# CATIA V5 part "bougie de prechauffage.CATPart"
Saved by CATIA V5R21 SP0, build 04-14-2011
Part number: bougie de prechauffage
Material "Laiton": density 8216 kg/m3, Young's modulus 1.31e+11 Pa, Poisson ratio 0.35, thermal expansion 1.67e-05 1/K
Bounding box of the stored display mesh (mm): x -4 to 4, y -4.619 to 4.619, z 0 to 15.5
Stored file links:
  C:\Users\Olivier\Desktop\redaction CATIA (local)\pompe à moteur de ventilation refait\bougie de prechauffage.CATPart
  C:\Program Files\Dassault Systemes\B21\win_b64\startup\materials\French\Catalog.CATMaterial
  C:\Users\Olivier\Desktop\redaction CATIA (local)\pompe à moteur de ventilation refait\Pompe_a_moteur_de_ventilation.CATProduct
  C:\Users\Olivier\Desktop\redaction CATIA (local)\pompe à moteur de ventilation refait\Ecrou a collerette M5.CATPart
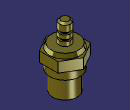
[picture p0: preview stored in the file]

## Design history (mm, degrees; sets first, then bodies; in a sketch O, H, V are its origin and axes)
Body1 (main body), material "Laiton"
  Sketch1 on yz-plane, origin (0, 0, 0), H (0, 1, 0), V (0, 0, 1)
    point P1 (3.021, 0)
    line L1 (3, 5) -> (3.75, 5)
    line L2 (3.75, 5) -> (3.75, 9.5)
    line L3 (3.75, 9.5) -> (3.3999, 10.5)
    line L4 (3.3999, 10.5) -> (1.4, 10.5)
    line L5 (1.4, 10.5) -> (1.4, 11.4933)
    line L6 (1.4, 11.4933) -> (0.9847, 11.4933)
    line L7 (0.9847, 11.4933) -> (0.9847, 11.9933)
    line L8 (0.9847, 11.9933) -> (1.4, 11.9933)
    point P10 (1.4, 11.9933)
    line L9 (1.4, 11.9933) -> (1.4, 12.9933)
    line L10 (1.4, 12.9933) -> (0.9847, 12.9933)
    point P12 (0.9847, 12.9933)
    line L11 (0.9847, 12.9933) -> (0.9847, 13.4933)
    line L12 (0.9847, 13.4933) -> (1.4, 13.4933)
    point P14 (1.4, 13.4933)
    line L13 (2.5869, 0) -> (1.25, 0)
    line L14 (1.25, 0) -> (1.25, 4)
    line L15 (1.25, 4) -> (0, 4)
    point P17 (0, 4)
    line L16 (3, 5) -> (3.02, 0.25)
    line L17 (2.5869, 0) -> (3.02, 0.25)
    line L18 (1.4, 13.4933) -> (1.4, 15.0655)
    point P20 (1.4, 15.5)
    line L19 (0.9655, 15.5) -> (0, 15.5)
    point P21 (0, 15.5)
    line L20 (0.9655, 15.5) -> (1.4, 15.0655)
    distance L14 V = 1.25
    distance L1 H = 5
    length L2 = 4.5
    length L11 = 0.5
    length L7 = 0.5
    length L9 = 1
    distance L2 V = 3.75
    length L3 V = 1
    angle L13 L17 = 30
    length L17 = 0.5
    length L14 = 4
    distance L19 H = 15.5
    distance P20 P21 = 1.4
    angle L19 L20 = 45
    length L20 = 0.6144
    coincidence: P1 H, P10 L5, P12 L7, P14 L5, P17 V, L13 P1, L16 P1, P21 V, L19 P20, L18 P20
    horizontal: L1 H, L4 H, L6 H, L8 H, L10 H, L12 H, L13 H, L15 H, L19 H
    vertical: L2 V, L5 V, L7 V, L9 V, L11 V, L14 V, L18 V
  Shaft1: profile Sketch1, axis Sketch1.V, angle 360
  Plane1: type Offset, RefPlane xy-plane, Offset 7
  Sketch2 on Plane1, origin (0, 0, 7), H (1, 0, 0), V (0, 1, 0)
    point P1 (4, -2.3094)
    point P2 (4, 2.3094)
    point P3 (0, 4.6188)
    point P4 (-4, 2.3094)
    point P5 (-4, -2.3094)
    point P6 (0, -4.6188)
    point P7 (4, 0)
    line L1 (4, -2.3094) -> (4, 2.3094)
    line L2 (4, 2.3094) -> (0, 4.6188)
    line L3 (0, 4.6188) -> (-4, 2.3094)
    line L4 (-4, 2.3094) -> (-4, -2.3094)
    line L5 (-4, -2.3094) -> (0, -4.6188)
    line L6 (0, -4.6188) -> (4, -2.3094)
    construction line L7 (0, 0) -> (4, 0)
    construction circle A1 centre (0, 0) radius 4.6188
    construction arc A2 centre (-4, -2.3094) radius 4.6188 from (-4, 2.3094) to (0, -4.6188) cw
    construction arc A3 centre (4, 2.3094) radius 4.6188 from (0, 4.6188) to (4, -2.3094) ccw
    distance L1 L4 = 8
    horizontal: L7 H
    coincidence: A1 P1, A1 P2, A1 P3, A1 P4, A1 P5, A1 P6, A2 O, A3 O
    midpoint: P7 L1
    parallelism: L1 L4
  Pad1: profile Sketch2, direction (0, 0, 1), length 2.5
